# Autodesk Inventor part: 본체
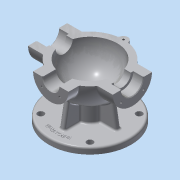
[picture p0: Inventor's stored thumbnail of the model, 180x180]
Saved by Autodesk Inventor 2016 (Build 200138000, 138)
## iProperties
Created: 2015-12
Part Number: 본체
Material: 알루미늄 6061
Document SubType Name: Modeling
Designer: mduedu
Density: 2.71 g/cm^3
Appearance: 알루미늄 - 평지
Mass: 966.367 g
Surface Area: 788.536 cm^2
Volume: 356.593 cm^3
Author: mduedu
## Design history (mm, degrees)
sketch "스케치1"
  geometry: L1 (-53, 0)-(53, 0); A1 r 53 centre (0, 0) between (53, 0) and (-53, 0); 2 further points
  constraints: 2 coincident, 2 end point, 2 point on circle, 1 centre point, 1 horizontal, 1 midpoint
  dimensions: "d0" = 53 radius of A1
revolve "회전1" sketch "스케치1" stored, may be unused: angle "d2" = 90 deg
feature "쉘1" dims "d11" = 10
node "작업 평면1"
sketch "스케치2"
  geometry: C1 r 31 at (0, 0); 1 further point
  constraints: 1 centre point, 1 coincident
  dimensions: "d4" = 62 diameter of C1
extrude "돌출1" join sketch "스케치2" stored distance "d5" = 10; taper "d6" = 0 deg
node "작업 평면2"
sketch "스케치3"
  geometry: C1 r 28 at (0, 0); 1 further point
  constraints: 1 centre point, 1 coincident
  dimensions: "d8" = 56 diameter of C1
extrude "돌출2" join sketch "스케치3" stored distance "d9" = 10; taper "d10" = 0 deg
hole "구멍1" diameter "d14" = 35; stored, may be unused: countersink angle "d18" = 90 deg, drill point angle "d20" = 0 deg; dims "d12" = 10, "d13" = 10, "d15" = 6, "d16" = 4, "d17" = 2, "d19" = 16
hole "구멍2" diameter "d23" = 27; stored, may be unused: countersink angle "d27" = 90 deg, drill point angle "d29" = 0 deg; dims "d21" = 10, "d22" = 10, "d24" = 6, "d25" = 4, "d26" = 2, "d28" = 16
fillet "모깎기1" dims "d30" = 0.3
hole "구멍3" diameter "d33" = 26; stored, may be unused: countersink angle "d37" = 90 deg, drill point angle "d39" = 0 deg; dims "d31" = 10, "d32" = 10, "d34" = 6, "d35" = 4, "d36" = 2, "d38" = 16
chamfer "모따기1" distance "d40" = 1; stored, may be unused: second distance "d41" = 2, angle "d42" = 45 deg
sketch "스케치4"
  geometry: L1 (0, 0)-(0, -25); L2 (0, 0)-(-17.678, -17.678); A1 r 25 centre (0, 0) between (-17.678, -17.678) and (0, -25); 1 further point
  constraints: 4 end point, 2 point on circle, 1 centre point, 1 coincident, 1 vertical
  dimensions: "d43" = 50 diameter of A1; "d47" = 45 deg angle of L1 L2
hole "구멍4" sketch "스케치4" at (-17.678, -17.678) diameter "d49" = 3.242; stored, may be unused: countersink angle "d53" = 90 deg, drill point angle "d55" = 118 deg; dims "d50" = 11, "d51" = 4, "d52" = 2, "d54" = 13
sketch "스케치5"
  geometry: L1 (0, 0)-(0, -20); L2 (0, 0)-(-14.142, -14.142); A1 r 20 centre (0, 0) between (0, -20) and (-14.142, -14.142); 2 further points
  constraints: 4 end point, 2 coincident, 2 point on circle, 1 centre point, 1 vertical
  dimensions: "d59" = 40 diameter of A1; "d65" = 45 deg angle of L1 L2
hole "구멍5" sketch "스케치5" at (-14.142, -14.142) diameter "d67" = 3.242; stored, may be unused: countersink angle "d71" = 90 deg, drill point angle "d73" = 118 deg; dims "d68" = 8, "d69" = 4, "d70" = 2, "d72" = 10
node "작업 평면3"
sketch "스케치6"
  geometry: C1 r 65 at (0, 0); 1 further point
  constraints: 1 centre point, 1 coincident
  dimensions: "d78" = 130 diameter of C1
extrude "돌출3" join sketch "스케치6" distance "d80" = 10; taper "d81" = 0 deg
sketch "스케치7"
  geometry: C1 r 20 at (0, 0); 1 further point
  constraints: 1 centre point, 1 coincident
  dimensions: "d82" = 40 diameter of C1
extrude "돌출4" join sketch "스케치7" stored distance "d84" = 10; taper "d85" = 0 deg
sketch "스케치8"
  geometry: 2 further points
  constraints: 1 coincident
hole "구멍6" sketch "스케치8" at (0, 0) diameter "d86" = 20; stored, may be unused: countersink angle "d90" = 90 deg, drill point angle "d92" = 118 deg; dims "d87" = 7, "d88" = 40, "d89" = 5, "d91" = 10
fillet "모깎기2" dims "d93" = 0.3
sketch "스케치9"
  geometry: L1 (65, -75)-(-65, -75) reference; L2 (-45, -75)-(-38.245, -36.692); A1 r 53 centre (0, 0) between (42.988, 31) and (42.988, -31) reference; 1 further point
  constraints: 2 end point, 1 point on circle, 1 point on line
  dimensions: "d94" = 45 horizontal distance of L2.start point (0, 0); "d95" = 80 deg angle of L2 L1
feature "리브1" sketch "스케치9" dims "d96" = 1, "d97" = 8, "d98" = 0, "d99" = 0, "d100" = 1, "d101" = 1
sketch "스케치10"
  geometry: L1 (0, 0)-(0, -55); L2 (0, 0)-(-38.891, -38.891); A1 r 55 centre (0, 0) between (0, -55) and (-38.891, -38.891); 2 further points
  constraints: 4 end point, 2 coincident, 2 point on circle, 1 centre point, 1 vertical
  dimensions: "d105" = 110 diameter of A1; "d107" = 45 deg angle of L1 L2
hole "구멍7" sketch "스케치10" at (-38.891, -38.891) diameter "d109" = 10; stored, may be unused: countersink angle "d113" = 90 deg, drill point angle "d115" = 118 deg; dims "d110" = 7, "d111" = 40, "d112" = 5, "d114" = 10
fillet "모깎기3" dims "d120" = 3
fillet "모깎기4" dims "d121" = 3, "d122" = 3
fillet "모깎기5" dims "d123" = 3
fillet "모깎기6" dims "d124" = 3
sketch "스케치11"
  geometry: C1 r 5 at (-38.891, 38.891) reference; C2 r 5 at (38.891, 38.891) reference; C3 r 5 at (38.891, -38.891) reference; C4 r 5 at (-38.891, -38.891) reference; C5 r 20 at (0, 0) reference; C6 r 65 at (0, 0) reference; 1 further point
  constraints: 3 other
feature "엠보싱1" sketch "스케치11" dims "d125" = 0.5, "d126" = 0
sketch "스케치12"
  geometry: L1 (0, 100)-(0, -100); L2 (0, 100)-(100, 100); L3 (100, 100)-(100, -100); L4 (100, -100)-(0, -100); 2 further points
  constraints: 8 end point, 3 perpendicular, 1 coincident, 1 midpoint, 1 vertical
  dimensions: "d127" = 200 distance of L2.end L3.end; "d129" = 100 distance between parallel lines of L1 L3
extrude "돌출5" cut sketch "스케치12" stored distance "d130" = 10; taper "d131" = 0 deg
sketch "스케치13"
  geometry: C1 r 7 at (0, 53); A1 r 53 centre (0, 0) between (42.113, 32.179) and (-42.113, 32.179) reference; 1 further point
  constraints: 1 centre point, 1 point on circle
  dimensions: "d132" = 14 diameter of C1
extrude "돌출6" join sketch "스케치13" distance "d134" = 15; taper "d135" = 0 deg
hole "구멍8" diameter "d139" = 3.242; stored, may be unused: countersink angle "d143" = 90 deg, drill point angle "d145" = 118 deg; dims "d140" = 8, "d141" = 4, "d142" = 2, "d144" = 10, "d148" = 10, "d149" = 10
fillet "모깎기7" dims "d146" = 3
fillet "모깎기8" dims "d147" = 3
node "솔리드1"
mirror "대칭1"
mirror "대칭2"
pattern_circular "원형 패턴1" dims angle "d57" = 360 deg
mirror "대칭3"
pattern_circular "원형 패턴2" dims angle "d75" = 360 deg
pattern_circular "원형 패턴3" dims angle "d103" = 360 deg
pattern_circular "원형 패턴4" dims angle "d118" = 360 deg
node "투영된 루프1"
other parameters: "d3" = 67, "d7" = 62, "d77" = -85
